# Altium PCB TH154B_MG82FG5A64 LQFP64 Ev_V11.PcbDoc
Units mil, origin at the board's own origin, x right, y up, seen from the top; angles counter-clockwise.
Board outline 2850 x 2110 mil, 2 copper layers (Top Layer, Bottom Layer); 55 components, 79 nets, 354 pads, 133 vias.
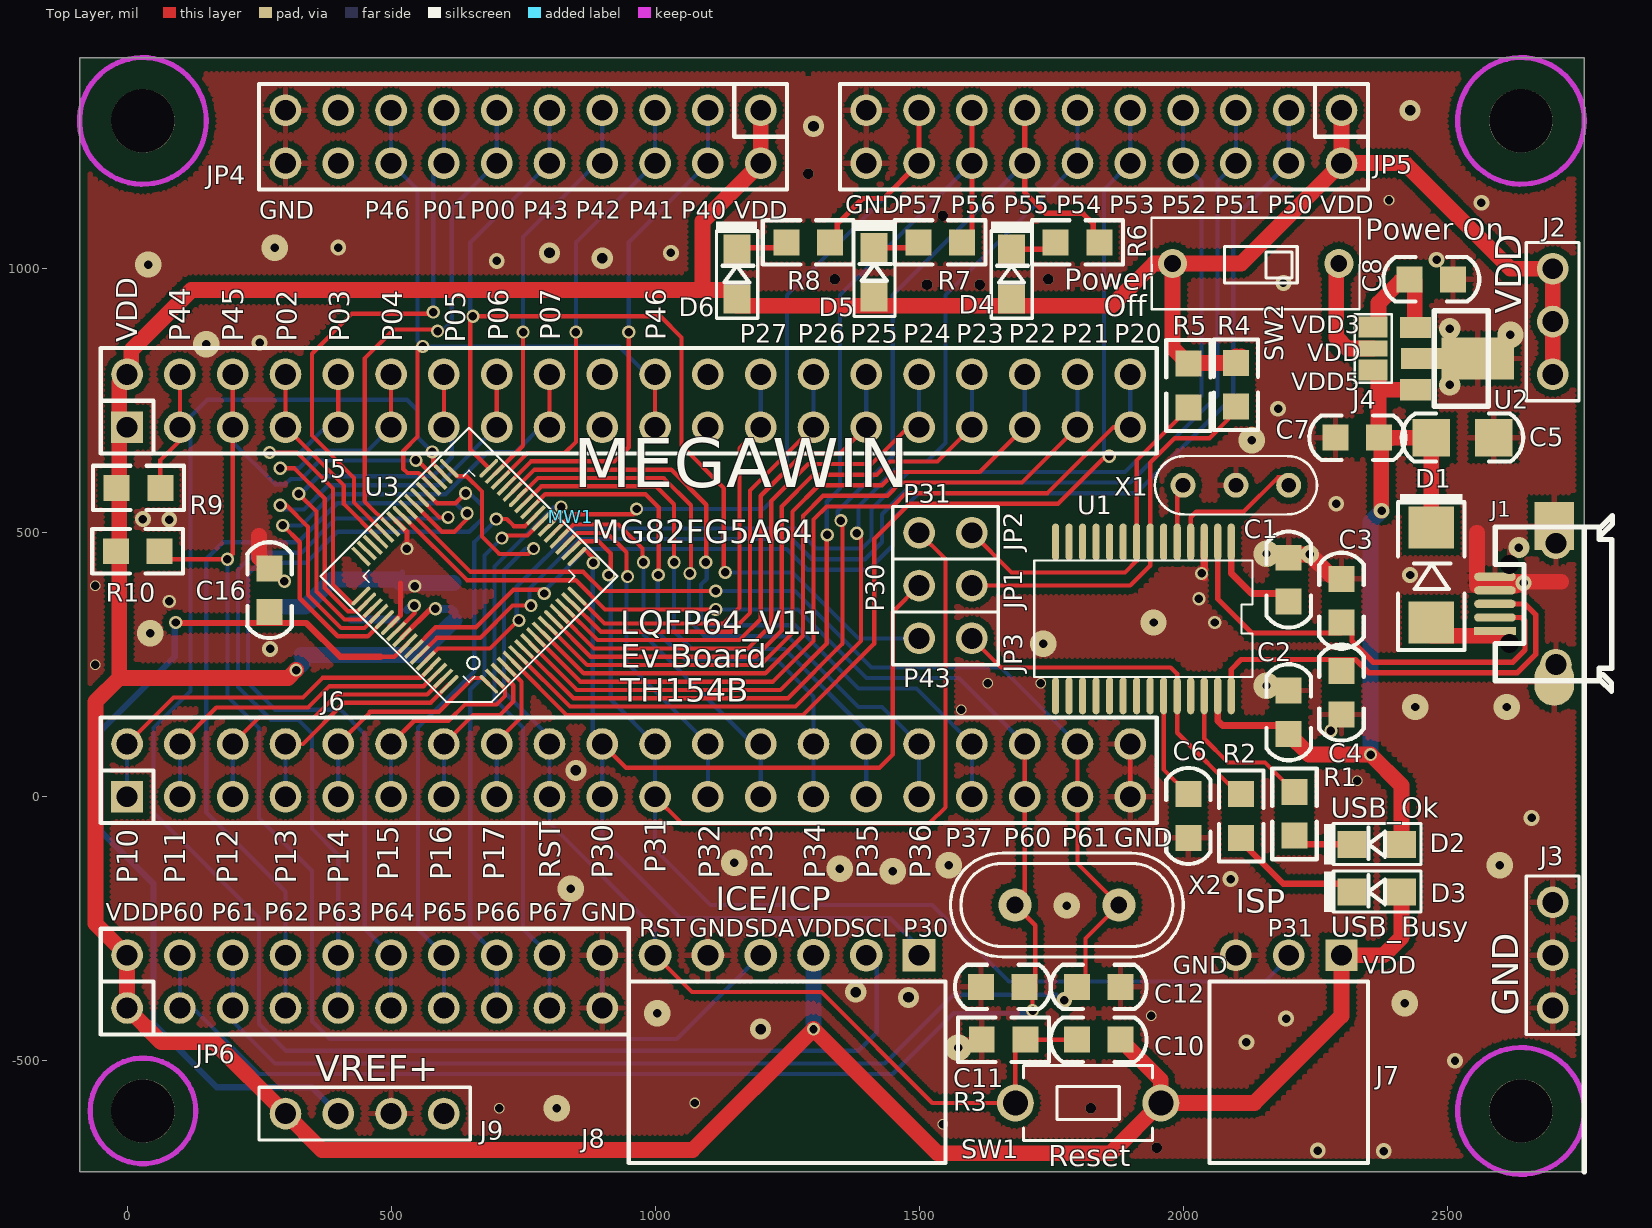
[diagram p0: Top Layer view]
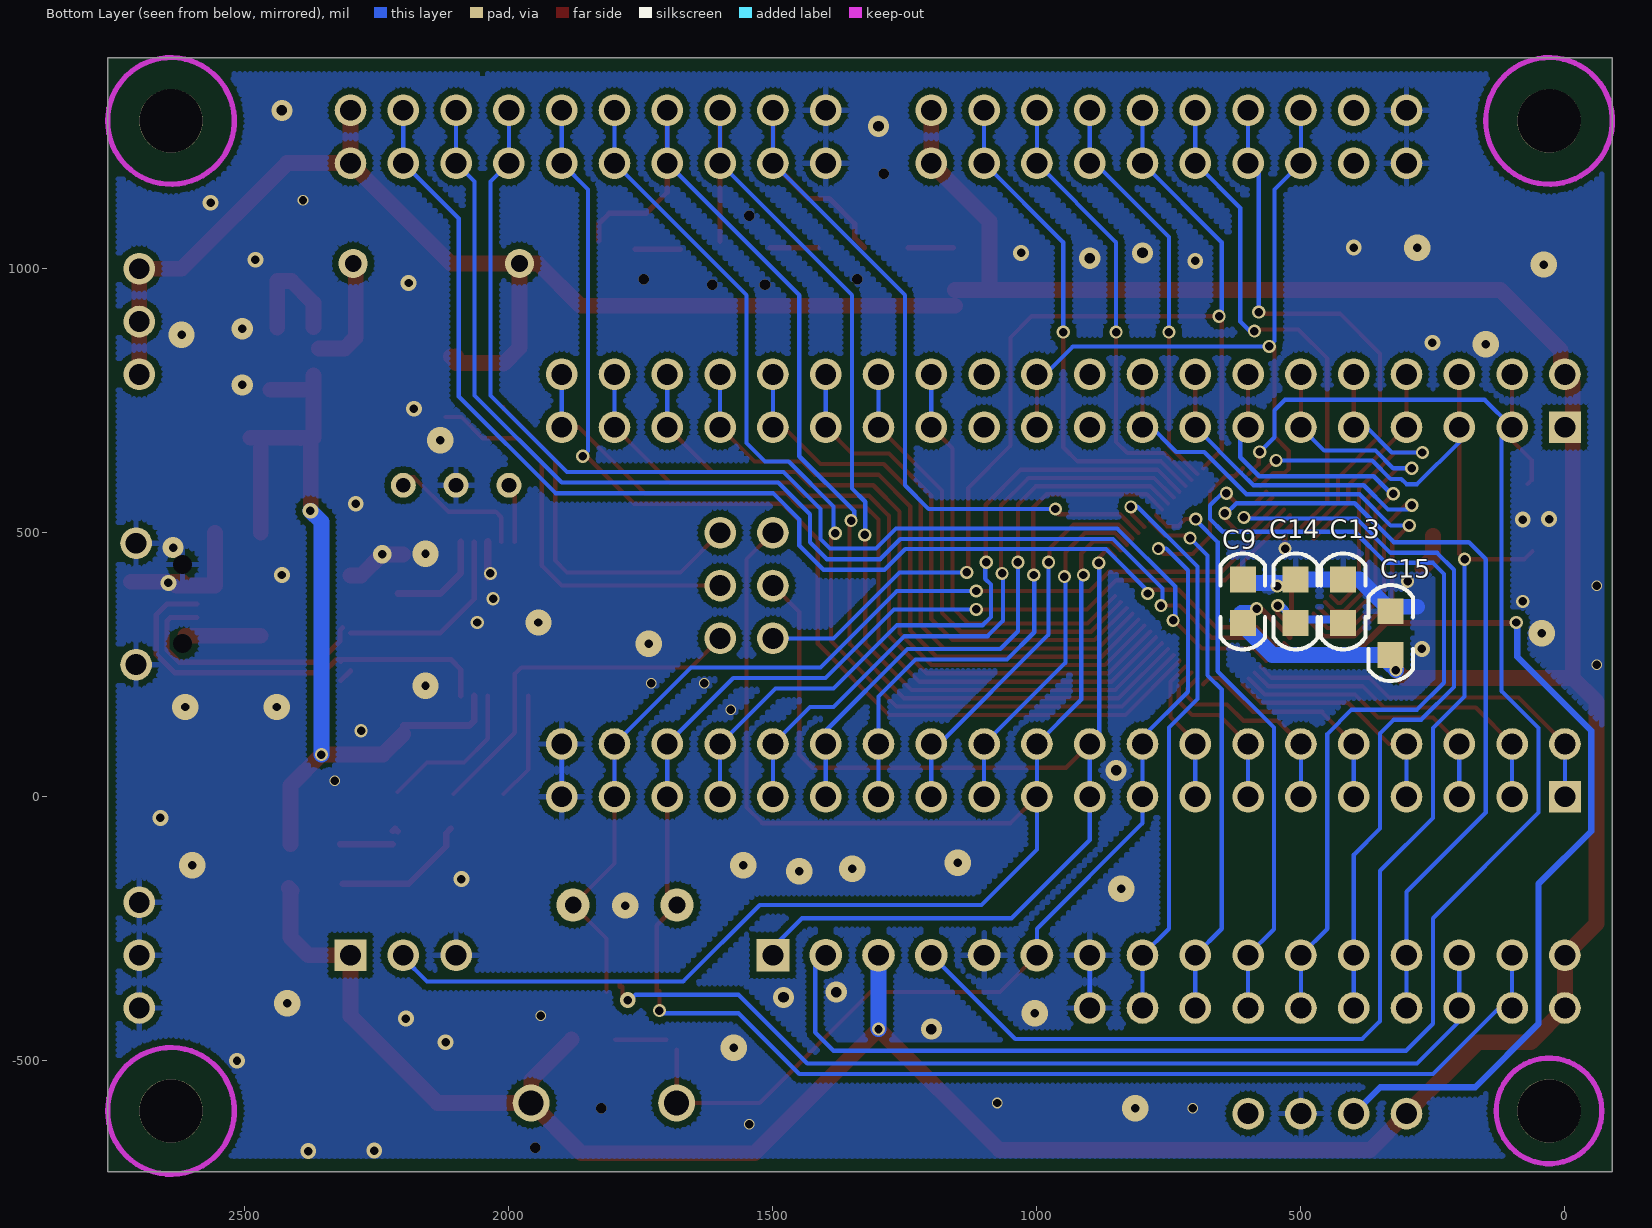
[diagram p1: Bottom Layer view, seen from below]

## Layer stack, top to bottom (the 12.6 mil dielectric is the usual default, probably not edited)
Top Layer: signal copper 1.4
Dielectric: dielectric 12.6, FR-4, Dk 4.8
Bottom Layer: signal copper 1.4

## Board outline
-90,-710 -90,1400 2760,1400 2760,-710

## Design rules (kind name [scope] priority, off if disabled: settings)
Clearance 12 [All] p1 off: gap=12
Clearance 10 [All] p2 off: gap=10
Clearance 6 [All] p3: gap=6
ComponentClearance [All] p1 off: gap=10 collisioncheckmode=3 verticalgap=10 showdistances=FALSE
HoleSize [All] p1: absolutevalues=TRUE maxlimit=500 minlimit=1 maxpercent=80.000 minpercent=20.000
MinimumSolderMaskSliver [All] p1 off: minsoldermaskwidth=10
PolygonConnect VIA [ISVIA] p1: connectstyle=Direct reliefconductorwidth=10 reliefentries=4 polygonreliefangle="90 Angle"
PolygonConnect [All] p2: connectstyle=Relief reliefconductorwidth=10 reliefentries=4 polygonreliefangle="90 Angle"
RoomDefinition "TH154B_MG82FG5A64 LQFP64 Ev_V10" [InComponentClass('TH154B_MG82FG5A64 LQFP64 Ev_V10')] p1: confinementstyle=ConfineIn formatcopy=TRUE lockcomponents=FALSE outline -510,-1145 3015,-1145 3015,1600 -510,1600
RoutingVias [All] p1: holewidth=16 width=25 viastyle="Through Hole" minholewidth=16 minwidth=24 maxholewidth=28 maxwidth=50
SilkToSilkClearance [All] p1 off: silktosilkclearance=10
SilkscreenOverComponentPads [All] p1 off: minsilkscreentomaskgap=10
SolderMaskExpansion [All] p1 off: expansion=4
Width [All] p1: maxlimit=200 minlimit=6 preferedwidth=10
23 further rules are at their usual default settings.

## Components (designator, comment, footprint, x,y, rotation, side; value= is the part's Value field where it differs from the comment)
C1 "4.7uF" 0805C 2200,411.34 r90 top
C2 "0.1uF" 0805C 2200,160 r270 top
C3 "15pF" 0805C 2300,371.34 r90 top
C4 "15pF" 0805C 2300,197.17 r270 top
C5 "4.7uF" 1206C 2529.06,680 r0 top
C6 "0.1uF" 0805C 2010,-36.34 r90 top
C7 "0.1uF" 0805C 2330,680 r180 top
C8 "4.7uF" 0805C 2470,980 r0 top
C9 "0.1uF" 0805C 610,370 r270 bottom
C10 "1u" 0805C 1840,-460 r180 top
C11 "NC" 0805C 1658.66,-360 r180 top
C12 "NC" 0805C 1840,-360 r0 top
C13 "4.7uF" 0805C 420,370 r90 bottom
C14 "0.1uF" 0805C 510,370 r270 bottom
C15 "4.7uF" 0805C 330,310 r90 bottom
C16 "0.1uF" 0805C 270,391.34 r90 top
D1 "1N5817" D5817_SMD_1 2470,420 r270 top
D2 "Yellow" 0805D 2366.92,-90 r180 top
D3 "Red" 0805D 2366.92,-180 r180 top
D4 "Green" 0805D 1675,990 r90 top
D5 "Red" 0805D 1415,993.08 r90 top
D6 "Green" 0805D 1155,990 r90 top
J1 "Micro USB母座" JACK_USB_SMD290X220P065 2590.71,365.28 r180 top
J2 "*" PS3P254 2700,800 r90 top
J3 "*" PS3P254 2700,-200 r270 top
J4 "*" JUMP3_SMD 2360,849 r90 top
J5 "*" PS20X2P254 0,700 r0 top
J6 "*" PS20X2P254 0,0 r0 top
J7 "*" PS3P254f_90 2300,-300 r180 top
J8 "*" PS6P254F_90 1500,-300 r180 top locked
J9 "CON4" PS4P254 300,-600 r0 top
JP1 "JUMPER2" PS2P254 1500,400 r0 top
JP2 "JUMPER2" PS2P254 1500,500 r0 top
JP3 "JUMPER2" PS2P254 1500,300 r0 top
JP4 "*" PS10X2P254 1200,1300 r180 top
JP5 "*" PS10X2P254 2300,1300 r180 top
JP6 "*" PS10X2P254 0,-400 r0 top
MW1 "MW-A4" MEGAWIN_T 840,530 r0 top
R1 "1K" 0805R 2211,-32.34 r270 top
R2 "1K" 0805R 2110,-36.34 r270 top
R3 "47K" 0805R 1660,-460 r0 top
R4 "4.7K" 0805R 2100,780.34 r270 top
R5 "4.7K" 0805R 2010,779 r270 top
R6 "1K" 0805R 1800,1050 r180 top
R7 "1K" 0805R 1540,1050 r180 top
R8 "1K" 0805R 1290,1050 r180 top
R9 "4.7K" 0805R 21.66,585 r180 top
R10 "4.7K" 0805R 20,465 r180 top
SW1 "SW TACT-SPST" SW_T_2P 1820,-580 r180 top
SW2 "-" DIP2_SW 2294.96,1010 r180 top
U1 "MA101_TSSOP28" SSOP28_220P065 1924.84,336.85 r180 top
U2 "AIC1734-33(SOT-89)" SOT89 2440,830 r270 top
U3 "MG82FG5A64" QFP64_7X7P040 647.58,417.62 r135 top (schematic designator U1)
X1 "6MHz" X3P 2200,590 r180 top
X2 "NC" X49U 1780,-205 r180 top

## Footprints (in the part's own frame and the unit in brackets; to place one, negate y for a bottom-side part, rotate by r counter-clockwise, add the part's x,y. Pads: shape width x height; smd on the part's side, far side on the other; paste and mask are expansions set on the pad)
0805C [mm]
  rect 1.25x1.25 smd: 1(-1.05,0) 2(1.05,0)
  silkscreen extent -2.31,-1.07 2.31,1.07
0805D [mm]
  rect 1.4x1.3 smd: 1(-1.192,0) 2(1.192,0)
  silkscreen extent -2.12,-1 2.53,0.98
0805R [mm]
  rect 1.25x1.25 smd: 1(-1.05,0) 2(1.05,0)
  silkscreen extent -2.18,-1.07 2.18,1.07
1206C [mm]
  rect 1.8x1.8 smd: 1(-1.5,0) 2(1.5,0)
  silkscreen extent -2.92,-1.15 2.92,1.16
D5817_SMD_1 [mil]
  rect 80x86.61 smd: 1(90,0) 2(-90,0)
  silkscreen extent -153,-63 142,63
DIP2_SW [mm]
  round 1.4 hole 0.8: 1(0,0) 2(8,0)
  silkscreen extent -1.02,-2.2 9.02,2.2
JACK_USB_SMD290X220P065 [mm]
  rect 1.9x1.8 on Mech2: 0(-2.85,-1.15) 0(-2.85,1.15)
  round 0.8 hole 0.9 unplated: 1(-0.7,1.9) 5(-0.7,-1.9)
  rect 2x0.4 smd: 1(0,1.3)
  oval 2x0.4 smd: 2(0,0.65) 3(0,0) 4(0,-0.65) 5(0,-1.3)
  round 1.524 hole 1: 5(-2.931,2.921) 5(-2.931,-2.921)
  oval 1.9x2.3 smd: 5(-2.85,3.75)
  rect 1.9x2.3 smd: 5(-2.85,-3.75)
  silkscreen extent -5.65,-4.25 -0.01,4.2
JUMP3_SMD [mil]
  rect 40x55 smd: 1(-41,0) 3(41,0)
  rect 30x55 smd: 2(0,0)
  silkscreen extent -65,-35 65,35
MEGAWIN_T [mil]
PS2P254 [mil]
  round 60 hole 39.37: 1(0,0) 2(100,0)
  silkscreen extent -50,-50 150,50
PS3P254 [mil]
  round 60 hole 39.37: 1(0,0) 2(100,0) 3(200,0)
  silkscreen extent -50,-50 250,50
PS3P254f_90 [mil]
  rect 60x60 hole 39.37: 1(0,0)
  round 60 hole 39.37: 2(100,0) 3(200,0)
  silkscreen extent -50,50 250,394
PS4P254 [mil]
  round 60 hole 39.37: 1(0,0) 2(100,0) 3(200,0) 4(300,0)
  silkscreen extent -50,-50 350,50
PS6P254F_90 [mil]
  rect 62x62 hole 39.37: 1(0,0)
  round 62 hole 39.37: 2(100,0) 3(200,0) 4(300,0) 5(400,0) 6(500,0)
  silkscreen extent -50,50 550,394
PS10X2P254 [mil]
  round 60 hole 39.37: 1(0,0) 2(0,100) 3(100,0) 4(100,100) 5(200,0) 6(200,100) 7(300,0) 8(300,100) 9(400,0) 10(400,100) 11(500,0) 12(500,100) 13(600,0) 14(600,100) 15(700,0) 16(700,100) 17(800,0) 18(800,100) 19(900,0) 20(900,100)
  silkscreen extent -50,-50 950,150
PS20X2P254 [mil]
  rect 60x60 hole 39.37: 1(0,0)
  round 60 hole 39.37: 2(0,100) 3(100,0) 4(100,100) 5(200,0) 6(200,100) 7(300,0) 8(300,100) 9(400,0) 10(400,100) 11(500,0) 12(500,100) 13(600,0) 14(600,100) 15(700,0) 16(700,100) 17(800,0) 18(800,100) 19(900,0) 20(900,100) 21(1000,0) 22(1000,100) 23(1100,0) 24(1100,100) 25(1200,0) 26(1200,100) 27(1300,0) 28(1300,100) 29(1400,0) 30(1400,100) 31(1500,0) 32(1500,100) 33(1600,0) 34(1600,100) 35(1700,0) 36(1700,100) 37(1800,0) 38(1800,100) 39(1900,0) 40(1900,100)
  silkscreen extent -50,-50 1950,150
QFP64_7X7P040 [mm]
  oval 1.2x0.19 smd: 1(-4.35,3) 12(-4.35,-1.4) 16(-4.35,-3) 33(4.35,-3) 34(4.35,-2.6) 38(4.35,-1) 41(4.35,0.2)
  rect 1.2x0.19 smd: 2(-4.35,2.6) 3(-4.35,2.2) 4(-4.35,1.8) 5(-4.35,1.4) 6(-4.35,1) 7(-4.35,0.6) 8(-4.35,0.2) 9(-4.35,-0.2) 10(-4.35,-0.6) 11(-4.35,-1) 13(-4.35,-1.8) 14(-4.35,-2.2) 15(-4.35,-2.6) 35(4.35,-2.2) 36(4.35,-1.8) 37(4.35,-1.4) 39(4.35,-0.6) 40(4.35,-0.2) 42(4.35,0.6) 43(4.35,1) 44(4.35,1.4) 45(4.35,1.8) 46(4.35,2.2) 47(4.35,2.6) 48(4.35,3)
  oval 0.19x1.2 smd: 17(-3,-4.35) 27(1,-4.35) 32(3,-4.35) 49(3,4.35) 50(2.6,4.35) 53(1.4,4.35) 54(1,4.35) 64(-3,4.35)
  rect 0.19x1.2 smd: 18(-2.6,-4.35) 19(-2.2,-4.35) 20(-1.8,-4.35) 21(-1.4,-4.35) 22(-1,-4.35) 23(-0.6,-4.35) 24(-0.2,-4.35) 25(0.2,-4.35) 26(0.6,-4.35) 28(1.4,-4.35) 29(1.8,-4.35) 30(2.2,-4.35) 31(2.6,-4.35) 51(2.2,4.35) 52(1.8,4.35) 55(0.6,4.35) 56(0.2,4.35) 57(-0.2,4.35) 58(-0.6,4.35) 59(-1,4.35) 60(-1.4,4.35) 61(-1.8,4.35) 62(-2.2,4.35) 63(-2.6,4.35)
  silkscreen extent -5.05,-5.05 5.05,5.05
SOT89 [mm]
  rect 1.016x1.5 smd: 1(-1.5,0) 3(1.5,0)
  rect 2x3.5 smd: 2(0,3)
  rect 1.016x2.6 smd: 2(0,0.6)
  silkscreen extent -2.3,0.9 2.3,3.5
SSOP28_220P065 [mil]
  oval 13.5x70 smd: 1(-166.34,-145.67) 2(-140.75,-145.67) 3(-115.16,-145.67) 4(-89.57,-145.67) 5(-63.98,-145.67) 6(-38.39,-145.67) 7(-12.79,-145.67) 8(12.8,-145.67) 9(38.39,-145.67) 10(63.98,-145.67) 11(89.57,-145.67) 12(115.16,-145.67) 13(140.75,-145.67) 14(166.34,-145.67) 15(166.34,145.67) 16(140.75,145.67) 17(115.16,145.67) 18(89.57,145.67) 19(63.98,145.67) 20(38.39,145.67) 21(12.8,145.67) 22(-12.79,145.67) 23(-38.39,145.67) 24(-63.98,145.67) 25(-89.57,145.67) 26(-115.16,145.67) 27(-140.75,145.67) 28(-166.34,145.67)
  silkscreen extent -207,-110 207,110
SW_T_2P [mil]
  round 70 hole 47.24: 1(-137.79,0) 2(137.79,0)
  silkscreen extent -122,-71 122,71
X3P [mm]
  round 1.2 hole 0.711: 1(0,0) 2(5.08,0) 3(2.54,0)
  silkscreen extent -1.36,-1.4 6.44,1.4
X49U [mm]
  round 1.6 hole 0.8: 1(-2.5,0) 2(2.5,0)
  silkscreen extent -5.6,-2.5 5.6,2.5

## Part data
C1 C5 C8 C13 C15: library part CAP
C2 C3 C4 C6 C7 C9 C14 C16: library part "CAP NP"
C10: library part C
C11 C12: library part "C NP"
D1: library part DIODE_ZD, "Schottky Diode"
D2 D3 D4 D5 D6: library part LED
J1: library part CON5, "Connector"
J2 J3 J4 J7: library part CON3
J5 J6: library part CON40A
J8: library part CON6
JP4 JP5 JP6: library part CON10X2
R1 R2 R4 R5 R6 R7 R8: library part R_Dup1
R3 R9 R10: library part R
SW2: library part SW-2
U2: library part AIC1734-33(SOT-89)_0
U3: library part MG82FG5A64_LQFP64
X1: library part CRYSTAL_RC
X2: library part CRYSTAL

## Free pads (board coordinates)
  round 120 hole 120 unplated: 0(30,-595) 0(30,1280) 0(2640,-595) 0(2640,1280)

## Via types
v1: diameter 25, hole 16, Top Layer to Bottom Layer, tented both sides, 56 vias
v2: diameter 30, hole 16, Top Layer to Bottom Layer, tented both sides, 23 vias
v3: diameter 50, hole 16, Top Layer to Bottom Layer, tented both sides, 23 vias
v4: diameter 20, hole 16, Top Layer to Bottom Layer, tented both sides, 11 vias
v5: diameter 20, hole 20, Top Layer to Bottom Layer, tented both sides, 8 vias
v6: diameter 40, hole 20, Top Layer to Bottom Layer, tented both sides, 8 vias
v7: diameter 40, hole 16, Top Layer to Bottom Layer, tented both sides, 3 vias
v8: diameter 35, hole 16, Top Layer to Bottom Layer, tented both sides, 1 vias

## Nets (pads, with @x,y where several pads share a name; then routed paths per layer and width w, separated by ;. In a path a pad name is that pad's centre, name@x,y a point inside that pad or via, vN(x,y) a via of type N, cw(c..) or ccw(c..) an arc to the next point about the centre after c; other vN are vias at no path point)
D+: C4.1 J1.3 U1.28 | length 850.7
  Top Layer w10: U1.28 2091.18,241.18 2110,260 2300,260 C4.1@2315,260 ; C4.1 C4.1@2318.51,220 ; C4.1@2318.24,256.76 C4.1@2315,260 ; J1.3 2647.64,365.28 2667.71,345.2 2667.71,269.55 2633.16,235 2351.72,235 2326.72,260 C4.1@2315,260
D-: C3.1 J1.2 U1.2 | length 865
  Top Layer w10: U1.2 2065.59,374.41 2130,310 C3.1@2300,310 ; C3.1@2315,320 2320,315 2320,295 2360,255 2624.87,255 2647.71,277.84 2647.71,333.12 2641.14,339.69 J1.2
GND_POWER: C1.2 C2.1 C3.2 C4.2 C5.2 C6.1 C7.2 C8.2 C9.1 C11.2 C12.2 C13.2 C14.1 C15.2 C16.2 J1.4 J1.5 J3.1 J3.2 J3.3 J6.39 J6.40 J7.3 J8.5 J9.3 JP4.19 JP4.20 JP5.19 JP5.20 JP6.19 JP6.20 R3.1 U1.3 U2.2 U3.42 U3.54 X1.3 | length 1339.3
  Top Layer w8: J6.39 J6.40
  Top Layer w10: U3.54 518,343.71 518,405.01 ; U3.42 530,501.79 v1@530,472.01
  Top Layer w15: v1@2040,416 2040,423 U1.3
  Top Layer w30: 250,494 250,452.68 C16.2 ; C1.2@2200,459 v8(2240,459) 2280,419 C3.2@2300,419 ; 2556.57,400.32 2590.71,400.32 2630,400.32 ; 2556.57,402.91 2556.57,416.46 2556.57,500 ; 2619.25,407.32 2645,407.32 2716.34,407.32
  Bottom Layer w8: JP6.19 JP6.20 ; J6.39 J6.40
  Bottom Layer w10: C14.1@521,405.01 521,411.34 C14.1@521,425.68
  Bottom Layer w30: 280,360 330,360 337.32,360 388.66,411.34 C13.2 C14.1 ; C14.1@518,405.01 521,405.01 545,405.01 610,405.01 C9.1@618,405.01
  other v1: 2280,125 2060,330 80,370 2030,375 545,399 298,408 2035,423 530,470
  other v2: 2380,-671 2255,-670 2515,-500 2120,-465 2195,-420 2090,-156 2660,-40 271,280 2645,405 2430,420 80,525 30,526 2290,555 2180,735 251,860 2190,972.99 700,1015 2480,1017 1030,1030 400,1040 2565,1125
  other v3: 814,-590 1574,-475 1004,-410 2420,-391 1780,-206 840,-174 1450,-141 1350,-136 1556,-130 2600,-130 1150,-125 2440,170 2612.91,170 2158,210 1735,290 44,310 1944,330 2158,460 2130,675 150,857 2620,875 40,1008 280,1040
  other v4: 1545,-620 705,-590 1075,-580 1940,-415 2330,30 1580,165 1630,215 1730,215 -60,250 -60,400 2390,1130
  other v5: 1950,-665 1825,-590 1515,970 1615,970 1340,980 1745,980 1545,1100 1290,1180
  other v6: 1200,-440 1480,-380 1380,-370 850,50 900,1020 800,1030 1300,1270 2430,1300
  other v7: 2636,472 2505,780 2505,886.37
MA101_RX: JP2.2 R5.2 U1.8 | length 683.4
  Top Layer w8: JP2.2 1675,425 1890,425 1912.05,447.05 U1.8 1912.05,637.05 2010,735 R5.2
MA101_TX: JP1.2 R4.2 U1.7 | length 766.4
  Top Layer w8: JP1.2 1900,400 1937.64,437.64 U1.7 1937.64,632.64 1984,679 2050,679 2090,719 2100,719 R4.2@2120,719
NetC1_1: C1.1 U1.1 | length 193.6
  Top Layer w13: U1.1 2091.18,423.82 2130,385 2200,385 C1.1@2210,385
NetC6_2: C6.2 U1.23 | length 205.6
  Top Layer w8: U1.23 1963.23,51.77 C6.2
NetC13_1: C13.1 C14.2 U3.55 | length 176.7
  Top Layer w8: U3.55 545,348.44 v1@545,362
  Bottom Layer w8: C14.2@510,335.5 C14.2@513.67,335.5 ; C14.2@530,352 530,354.01 ; v1@541.49,365.51 v1@545.99,370.01
  Bottom Layer w15: C13.1@425,335.5 C14.2@510,335.5 ; 530,354.01 540.99,365.01 v1@541.49,365.51
  other v1: 544,362
NetD1_1: D1.1 J1.1 | length 142.9
  Top Layer w30: D1.1@2470,305 2590.71,305 J1.1@2612.91,305
NetD2_2: D2.2 R1.2 | length 107.2
  Top Layer w12: R1.2@2210.6,-65 R1.2@2211,-65 ; R1.2@2215,-60 R1.2@2219.84,-64.84 ; R1.2@2220,-90 D2.2
NetD3_2: D3.2 R2.2 | length 263.1
  Top Layer w12: R2.2@2110,-60 2118.84,-68.84 2118.84,-77.68 2118.84,-93.84 2190,-165 D3.2@2315,-165
NetD4_2: D4.2 R6.2 | length 85.6
  Top Layer w10: D4.2 1758.66,1036.92 R6.2@1760.58,1036.92
NetD5_2: D5.2 R7.2 | length 90
  Top Layer w10: D5.2 1498.66,1040 R7.2@1505,1040
NetD6_2: D6.2 R8.2 | length 85.6
  Top Layer w10: D6.2@1158.08,1040 R8.2@1243.66,1040
NetJ4_2: J4.2 SW2.1 | length 217.8
  Top Layer w30: SW2.1@2300,1004.96 2290,994.96 2290,870 2311,849 J4.2
NetU1_4: U1.4 X1.1 | length 263.8
  Top Layer w8: U1.4 2014.41,529.41 2025,540 2115,540 2180,605 X1.1@2200,605
NetU1_5: U1.5 X1.2 | length 127.1
  Top Layer w8: U1.5 1988.82,590 1988.82,593.82 1992.5,597.5 X1.2@2000,605
P00: JP4.11 JP4.12 U3.43 | length 969.7
  Top Layer w8: U3.43 450,559.52 450,830 505,885 v1@585,885
  Bottom Layer w8: v1@585,882 v1(588,882) 597,882 615,900 615,1115 JP4.12 JP4.11
P01: JP4.13 JP4.14 U3.44 | length 1051
  Top Layer w8: U3.44 430,557.25 430,604 350,684 350,839 426,915 v1@580,915
  Bottom Layer w8: v1@580,915 v1(580,918) 580,1180 JP4.14 JP4.13
P02: J5.7 J5.8 U3.45 | length 404.5
  Top Layer w8: J5.8 J5.7 410.49,589.51 410.49,554.49 U3.45
  Bottom Layer w8: J5.7@280,700 J5.7
P03: J5.9 J5.10 U3.49 | length 652.9
  Top Layer w8: v1(270,652.01) 321.99,652.01 390,584 390,402 425.01,366.99 429.93,366.99 U3.49 ; J5.9 J5.10
  Bottom Layer w8: v1(270,652.01) 328.01,652.01 376,700 J5.9
P04: J5.11 J5.12 U3.50 | length 705
  Top Layer w8: v1@300,622.01 316.99,622.01 374.25,564.75 374.25,395.48 418.48,351.24 436.45,351.24 U3.50 ; J5.11 J5.12
  Bottom Layer w8: v1@300,622.01 325.01,622.01 359.01,656.01 456.01,656.01 J5.11
  other v1: 290,622.01
P05: J5.13 J5.14 U3.51 | length 818.8
  Top Layer w8: v1(325,574) 358.5,540.5 358.5,388.95 411.96,335.5 442.97,335.5 U3.51 ; J5.13 J5.14
  Bottom Layer w8: v1(325,574) 329,574 362.01,607.01 579,607.01 615,643.01 615,685 J5.13
P06: J5.15 J5.16 U3.52 | length 959.2
  Top Layer w8: v1(290,552.01) 301.99,552.01 342.76,511.24 342.76,382.43 405.44,319.75 449.5,319.75 U3.52 ; J5.15 J5.16
  Bottom Layer w8: v1(290,552.01) 298.01,544 335,544 381.01,590.01 590.01,590.01 612.55,612.55 ; 604,604 612.55,612.55 ; J5.15 612.55,612.55
P07: J5.17 J5.18 U3.53 | length 1026.8
  Top Layer w8: v1(295,514) 327.01,481.99 327.01,375.91 398.92,304 456.02,304 U3.53 ; J5.17@800,717.01 J5.18
  Bottom Layer w8: v1(295,514) 330,514 389.01,573.01 603,573.01 683.11,653.12 736.11,653.12 791.49,708.51 J5.17@800,717.01
P10: J6.1 J6.2 U3.61 | length 737.2
  Top Layer w8: J6.2 88.01,188.01 333,188.01 370.23,225.24 555.43,225.24 U3.61
  Bottom Layer w8: J6.1 J6.2
P11: J6.3 J6.4 U3.62 | length 643.8
  Top Layer w8: J6.4 169.01,169.01 343,169.01 383.48,209.5 561.95,209.5 U3.62
  Bottom Layer w8: J6.3 J6.4
P12: J6.5 J6.6 U3.63 | length 550.3
  Top Layer w8: J6.6 250,150 353.99,150 397.74,193.75 568.48,193.75 U3.63
  Bottom Layer w8: J6.5 J6.6
P13: J6.7 J6.8 U3.64 | length 534.5
  Top Layer w8: J6.8@327.73,100 J6.8 332.99,100 410.99,178 535,178 ; 485,178 535,178 ; U3.64 575,178 535,178
  Bottom Layer w8: J6.7 J6.8
P14: J6.9 J6.10 U3.1 | length 441.4
  Top Layer w8: J6.10 459.75,159.75 ; 459.75,161 591,161 655,225 673.16,225 U3.1
  Bottom Layer w8: J6.9 J6.10
P15: J6.11 J6.12 U3.2 | length 423.1
  Top Layer w8: J6.12@520,120 J6.12 544,144 609,144 640,175 700,175 715.75,190.75 715.75,204.69 U3.2
  Bottom Layer w8: J6.11 J6.12
P16: J6.13 J6.14 U3.3 | length 329.9
  Top Layer w8: J6.14@599.71,100 J6.14 655,155 706,155 731.5,180.5 731.5,211.21 U3.3
  Bottom Layer w8: J6.13 J6.14
P17: J6.15 J6.16 U3.4 | length 324.3
  Top Layer w8: J6.16 700,104 747.24,151.24 747.24,217.73 ; U3.4 747.24,217.73 ; 747.24,171.24 747.24,217.73
  Bottom Layer w8: J6.15 J6.16
P20: J5.39 J5.40 U3.9 | length 1595
  Top Layer w8: U3.9 858.33,218.01 1223.01,218.01 1300,295 1300,525 1325,550 1450,550 1475,575 1742.99,575 1867.99,700 J5.39
  Bottom Layer w8: J5.39 J5.40
P21: J5.37 J5.38 U3.10 | length 1473.6
  Top Layer w8: U3.10 864.85,233.76 1208.76,233.76 1280,305 1280,532.01 1317.99,570 1440,570 1465,595 1695,595 J5.37
  Bottom Layer w8: J5.37 J5.38
P22: J5.35 J5.36 U3.11 | length 1355.8
  Top Layer w8: U3.11 871.37,249.5 1199.5,249.5 1260,310 1260,540 1310,590 1430,590 1455,615 1615,615 J5.35
  Bottom Layer w8: J5.35 J5.36
P23: J5.33 J5.34 U3.12 | length 1239.2
  Top Layer w8: U3.12 877.89,265.25 1190.25,265.25 1240,315 1240,550 1300,610 1420,610 1445,635 1535,635 J5.33
  Bottom Layer w8: J5.33 J5.34
P24: J5.31 J5.32 U3.13 | length 1119.6
  Top Layer w8: U3.13 884.42,281 1176,281 1220,325 1220,560 1290,630 1410,630 1480,700 J5.31
  Bottom Layer w8: J5.31 J5.32
P25: J5.29 J5.30 U3.14 | length 1001
  Top Layer w8: U3.14 890.94,296.75 1160,296.75 1200,336.75 1200,570 1280,650 1350,650 J5.29 J5.29@1400,702.01
  Bottom Layer w8: J5.29 J5.30
P26: J5.27 J5.28 U3.15 | length 878.5
  Top Layer w8: U3.15 897.46,312.5 1144.15,312.5 1180,348.35 1180,580 J5.27
  Bottom Layer w8: J5.27 J5.28
P27: J5.25 J5.26 U3.16 | length 800
  Top Layer w8: U3.16 903.99,328.24 1130,328.24 1160,358.24 1160,660 J5.25
  Bottom Layer w8: J5.25 J5.26
P30/RXD: J6.19 J6.20 J8.1 JP1.1 U3.17 | length 2199
  Top Layer w8: U3.17 866,469 882,453 882,443 v1@882,442 ; J6.20 945,55 1425,55 1450,80 1450,350 JP1.1
  Bottom Layer w8: v1@882,442 882,118 J6.20 J6.19 900,-82 1048,-230 1445,-230 J8.1@1507.5,-292.5
  other v1: 883,443
P31/TXD: J6.21 J6.22 J7.2 JP2.1 U3.18 | length 3248.4
  Top Layer w8: U3.18 858.73,484 893,484 916,461 916,424 v1(912,420) ; J6.21 1050,-50 1520,-50 1550,-20 1550,450 JP2.1
  Bottom Layer w8: v1@916,420 916,184 J6.22 ; 920,180 J6.22 ; J7.2@2200,-305 2155,-350 1670,-350 1525,-205 1105,-205 1000,-100 J6.21 J6.22
P32: J6.23 J6.24 U3.19 | length 674.3
  Top Layer w8: U3.19 852.21,499.75 909.25,499.75 946,463 v1@946,417
  Bottom Layer w8: v1@946,424 946,417 946,254 J6.24 J6.23
  other v1: 948,417
P33: J6.25 J6.26 U3.20 | length 739.8
  Top Layer w8: U3.20 845.68,515.5 930.5,515.5 976,470 v1@976,455
  Bottom Layer w8: v1@974,444 976,442 978,440 978,307 1192.5,92.5 1200,85 J6.25
  other v1: 978,444
P34: J6.27 J6.28 U3.25 | length 1042
  Top Layer w8: U3.25 791.83,573 982,573 1007,548 v1@1007,420
  Bottom Layer w8: v1@1005,424 1005,420 1005,311.5 1056.5,260 1230,260 1300,190 J6.28 J6.27
  other v1: 1006,420
P35: J6.29 J6.30 U3.26 | length 1119.2
  Top Layer w8: U3.26 784.56,588 1002,588 1036,554 v1(1036,444)
  Bottom Layer w8: v1(1036,444) 1036,313.51 1069.51,280 1245,280 1400,125 J6.30 J6.29
P36: J6.31 J6.32 U3.27 | length 1215.2
  Top Layer w8: U3.27 778.04,603.75 1016.25,603.75 1068,552 v1@1068,424
  Bottom Layer w8: v1@1064,424 1064,423 1064,333.5 1093.32,304.17 1250.83,304.17 1385,170 1430,170 J6.32 J6.31
  other v1: 1066,423
P37: J6.33 J6.34 U3.28 | length 1344.7
  Top Layer w8: U3.28 771.51,619.5 1030.5,619.5 1097,553 v1@1097,444
  Bottom Layer w8: v1(1096,444) v1@1098,442 ; v1@1098,444 v1@1098,442 ; J6.33 J6.34 1495,205 1385,205 1265,325 1102.5,325 1087,340.5 1087,402 1098,413 v1@1098,442
P40: JP4.3 JP4.4 U3.29 | length 981.6
  Top Layer w8: U3.29 764.99,635.24 820,635.24 ; 839.76,635.24 820,635.24 ; v1(950,880) 950,662.01 923.23,635.24 820,635.24
  Bottom Layer w8: v1(950,880) 950,1050 JP4.4 JP4.3
P41: JP4.5 JP4.6 U3.30 | length 902
  Top Layer w8: U3.30 758.47,650.99 770,650.99 ; 809.5,650.99 770,650.99 ; v1(850,880) 850,672.01 828.98,650.99 770,650.99
  Bottom Layer w8: v1(850,880) 850,1050 JP4.6 JP4.5
P42: JP4.7 JP4.8 U3.31 | length 773.3
  Top Layer w8: U3.31 750,664.8 v1(750,880)
  Bottom Layer w8: v1(750,880) 750,1060 895,1205 900,1210 JP4.7
P43: JP3.1 JP4.9 JP4.10 U3.32 | length 2175.1
  Top Layer w8: 650,865 650,760 ; v1@650,905 v1@650,900 ; U3.32 650,657.4 650,760 ; v1@1130,425 1130,585 1050.03,664.97 1050.03,869.97 1010,910 660,910 657.5,907.5 v1@650,900 ; 650,760 v1@650,900
  Bottom Layer w8: v1@650,910 650,1050 JP4.10 JP4.9 ; v1@1130,425 v1(1133,425) 1260,425 1385,300 JP3.1
  other v1: 655,910
P44: J5.3 J5.4 J8.2 R9.1 U3.34 | length 3536.9
  Top Layer w8: R9.1@70.33,592.33 63,599.66 63,638 100,675 J5.3 J5.4 ; v1@580,647.01 580,629.96 U3.34
  Bottom Layer w8: v1(578,653.01) 550,681.01 550,732.01 530,752.01 152.01,752.01 J5.3 120,680 120,200 50,130 50,-30 250,-230 250,-430 301,-481 1385,-481 1420,-446 1420,-350 ; 1420,-440 1420,-350 ; J8.2@1420,-295 1420,-300 1420,-350
P45: J5.5 J5.6 J8.4 R10.1 U3.35 | length 2891.7
  Top Layer w8: R10.1 76.34,450 130,450 ; 150,450 130,450 ; J5.6 J5.5 200,460 v1(190,450) 130,450 ; v1@555,632.69 U3.35
  Bottom Layer w8: v1(190,450) 190,190 250,130 250,-40 350,-140 350,-425 384,-459 1041,-459 J8.4 ; J5.5 200,672.01 280,592.01 300,592.01 310,602.01 330.01,602.01 365.01,637.01 480,637.01 ; 443,637.01 480,637.01 ; v1(547,637.01) 480,637.01 ; v1@550,634.01 v1@551,635.01
P46: J5.21 J5.22 JP4.15 JP4.16 U3.36 | length 1343.9
  Top Layer w8: v1@550,853 550,682.01 523,655.01 523,621.01 530.87,613.14 552.28,613.14 U3.36 ; J5.21 J5.22
  Bottom Layer w8: JP4.15 JP4.16 550,1150 550,863 v1(560,853) 932,853 985,800 J5.22
P50: JP5.3 JP5.4 U3.58 | length 2405.1
  Top Layer w8: U3.58 584.37,321 661,321 732.01,392.01 782.99,392.01 v1(790,385)
  Bottom Layer w8: v1(790,385) 790,390 869,469 1249.43,469 1288.43,430 1404,430 1450,476 1450,525 1500,575 1912.01,575 2095,757.99 2095,1095 JP5.4 JP5.3
P51: JP5.5 JP5.6 U3.59 | length 2370.2
  Top Layer w8: U3.59 586.64,301 669,301 730,362 v1(765,362)
  Bottom Layer w8: v1(765,362) 767,364 762,369 762,394.26 855.74,488 1258.72,488 1296.72,450 1398,450 1430,482 1430,535 1490,595 1900,595 2065,760 2065,1165 JP5.6 ; JP5.5 JP5.6 ; JP5.6@2110,1190 JP5.6
P52: JP5.7 JP5.8 U3.60 | length 2340.7
  Top Layer w8: U3.60 588.92,281 687,281 741,335 v1@744,338
  Bottom Layer w8: v1@744,338 738,344 738,398 848,508 1267,508 1305,470 1392,470 1410,488 1410,545 1480,615 1890,615 2035,760 2035,1165 JP5.8 JP5.7
  other v1: 742,334
P53: JP5.9 JP5.10 U3.5 | length 2160.3
  Top Layer w8: U3.5 832.25,155 1280,155 1415,290 1415,488 1482,555 1762.99,555 v1@1850,642.01
  Bottom Layer w8: v1(1860,645) 1850,655 1850,1150 JP5.10 JP5.9
P54: JP5.11 JP5.12 U3.6 | length 1939.4
  Top Layer w8: U3.6 838.77,170.75 1265.75,170.75 1390,295 1390,499 1390,500 v1@1386.5,503.5
  Bottom Layer w8: v1@1385,510 1385,550 1470,635 1514.99,635 1550,670.01 1550,950 JP5.12 JP5.11
  other v1: 1382,499
P55: JP5.13 JP5.14 R6.1 U3.7 | length 2210.2
  Top Layer w8: U3.7 845.3,186.5 1251.5,186.5 1355,290 1355,523 v1@1355,524 ; JP5.13 JP5.13@1718.66,1281.34
  Top Layer w10: JP5.13 JP5.14 1700,1145 1740,1105 1810,1105 1830,1085 R6.1@1830,1053.26
  Bottom Layer w8: v1@1346,523 1346,541 1450,645 1450,950 JP5.14 JP5.13
  other v1: 1352,523
P56: JP5.15 JP5.16 R7.1 U3.8 | length 2019.2
  Top Layer w8: U3.8 851.82,202.24 1237.24,202.24 1325,290 v1@1325,490
  Top Layer w10: R7.1@1600,1052.32 JP5.16 ; JP5.15 JP5.16 ; JP5.16@1613.16,1186.84 JP5.16
  Bottom Layer w8: v1@1325,496 1325,558.73 1350,583.73 1350,950 JP5.16 JP5.15
  other v1: 1326,496
P57: JP5.17 JP5.18 R8.1 U3.21 | length 1647.3
  Top Layer w8: U3.21 842.92,535 959.5,535 965,540.5 v1@965.51,540.5
  Top Layer w10: R8.1@1326.34,1040 1333.84,1047.5 1345,1058.66 1345,1085 1392.99,1132.99 1432.99,1132.99 JP5.18 JP5.17
  Bottom Layer w8: v1(965,545) 1205,545 1250,590 1250,950 JP5.18 JP5.17
P60: C11.1 J6.35 J6.36 JP6.3 JP6.4 U3.41 X2.2 | length 3808.5
  Top Layer w8: U3.41 643.8,410.26 849.74,410.26 905.26,354.74 v1(1115,354.74) ; J6.36 J6.35 1700,-186.58 X2.2 1720,-243.42 1720,-360 C11.1@1720,-370 ; v1@1715,-410 v1(1715,-405) C11.1@1715,-368
  Bottom Layer w8: JP6.4 JP6.3 125,-400 250,-525 1450,-525 1565,-410 v1@1715,-410 ; v1(1115,354.74) 1270.41,354.74 1400.15,225 1575,225 J6.36 J6.35
P61: C12.1 J6.37 J6.38 JP6.5 JP6.6 U3.40 X2.1 | length 3902.4
  Top Layer w8: U3.40 650.32,426.01 863.99,426.01 900.26,389.74 v1(1115,389.74) ; v2@1785,-385 C12.1@1785,-360 ; C12.1@1790,-360 C12.1@1790,-353 ; J6.38 J6.37 1800,-126.58 X2.1 1815,-268.42 1815,-360 C12.1@1815,-370
  Bottom Layer w8: JP6.6 JP6.5 200,-425 280,-505 1435,-505 1565,-375 1760,-375 v2@1772.5,-387.5 ; v1(1115,389.74) 1265.26,389.74 1410,245 1655,245 J6.38 J6.37
  other v2: 1775,-385
P62: JP6.7 JP6.8 U3.39 | length 1635.3
  Top Layer w8: 567.53,531.08 U3.39 596.59,502.01 620.01,502.01 644,526 v1(644,537)
  Bottom Layer w8: JP6.7 JP6.8 300,-180 150,-30 150,450 182,482 324,482 398.01,556.01 622,556.01 v1@642.51,535.51
P63: JP6.9 JP6.10 U3.38 | length 1471.5
  Top Layer w8: U3.38 591.88,529 v1(608,529)
  Bottom Layer w8: JP6.9@400,-425 JP6.9 JP6.10 400,-110 350,-60 350,120 324,146 272.13,146 210,208.13 210,430 242,462 330,462 395.01,527.01 v1@608,527.01
P64: JP6.11 JP6.12 U3.37 | length 1649.6
  Top Layer w8: U3.37 587.14,556.01 622,556.01 v1(641,575.01)
  Bottom Layer w8: JP6.11 JP6.12 450,-250 450,119 404,165 280,165 229,216 229,422.13 249.87,443 339,443 398,502 648,502 672,526 672,551.99 v1@644.99,579
P65: JP6.13 JP6.14 U3.24 | length 1103.3
  Top Layer w8: v1@705,526 719,526 732.46,512.54 753.65,512.54 U3.24
  Bottom Layer w8: JP6.13 JP6.14 551,-251 551,131 657.71,237.71 657.71,482.71 695,520 699,520 705,520 705,526 v1@705,530
  other v1: 699,526
P66: JP6.15 JP6.16 U3.23 | length 1024.2
  Top Layer w8: v1(710,490) 715,495 758.37,495 U3.23
  Bottom Layer w8: JP6.15 JP6.16 650,-250 650,203 677,230 677,457 v1(710,490)
P67: JP6.17 JP6.18 U3.22 | length 1099.1
  Top Layer w8: U3.22 820,534.36 820,549 v1@820,550
  Bottom Layer w8: JP6.17 JP6.18 750,-250 750,131 696,185 696,436 810,550 v1@820,550
  other v1: 822,549
RST: C10.2 J6.17 J6.18 J8.6 R3.2 SW1.2 U3.33 | length 2243
  Top Layer w8: U3.33 625.31,606.92 643.09,606.92 672,578.01 672,493 705,460 ; 750,460 705,460 ; v1(770,470) 760,460 705,460 ; J8.6 1070,-370 1315,-370 1525,-580 SW1.2 R3.2@1682.21,-479.13 ; R3.2 C10.2
  Bottom Layer w8: v1(770,470) 755,470 714,429 714,199 800,113 J6.18 J6.17 800,-50 1000,-250 J8.6
USB_BUSY: JP3.2 R2.1 U1.24 | length 692.6
  Top Layer w8: JP3.2 1655,245 1976.61,245 1988.82,232.8 U1.24 1988.82,121.18 R2.1@2105,5
USB_OK: R1.1 U1.26 | length 294
  Top Layer w8: U1.26 2040,110 2085,65 2155,65 R1.1
VDD: C9.2 C10.1 C15.1 D3.1 D4.1 D5.1 D6.1 J2.1 J2.2 J2.3 J5.1 J5.2 J7.1 J8.3 J9.1 JP4.1 JP4.2 JP5.1 JP5.2 JP6.1 JP6.2 R4.1 R5.1 R9.2 R10.2 SW1.1 SW2.2 U3.56 | length 9370.2
  Top Layer w10: U3.56 v1@578.42,359.58
  Top Layer w30: -14.91,225.09 -14.91,465 -14.91,585 -14.91,700 -14.91,785.09 J5.2 ; J5.2@7.84,804.59 7.84,845.58 122.26,960 1090,960 ; v1(320,240) 305,225 -15,225 -60,180 -60,-240 JP6.2 JP6.1 65,-465 165,-465 J9.1 369,-669 1071,-669 v1(1300,-440) 1535,-675 1862.79,-675 SW1.1 ; D6.1@1155,930 1415,930 1675,930 1865,930 1945,1010 SW2.2 ; D6.1@1155,960 1090,960 ; JP4.1 JP4.2 1090,1090 1090,960 ; C10.1 1957.79,-536.46 SW1.1 ; R5.1 1980,850.34 SW2.2 ; R5.1@2011.34,821.68 R4.1 R4.1@2100,829 ; R4.1@2100,833.95 R4.1@2100,829 ; R4.1@2110,834.05 2104.95,829 R4.1@2100,829 ; J7.1@2300,-290 J7.1 ; JP5.1 JP5.2 ; D3.1@2411.92,-178.08 D3.1@2416.92,-173.08 ; D3.1 2413.84,-266.16 2380,-300 J7.1 ; J2.1 J2.2 J2.3 2620,1000 2420,1200 JP5.2 ; SW1.1 2135,-580 2300,-415 J7.1 ; SW2.2 2110,1010 JP5.2
  Bottom Layer w15: v1(584,356) 610,356 614.67,356 C9.2@620,350.67
  Bottom Layer w30: v1(320,240) C15.1@332.5,252.5 ; C15.1 554.31,268.66 612.15,326.51 C9.2@620,334.36 ; v1(1300,-440) J8.3
VDD3: C8.1 J4.3 U2.1 | length 218.7
  Top Layer w30: J4.3@2370,890 2370,935 2411.77,976.77 2428.66,976.77 2438.66,976.77 U2.1@2438.66,889.06
VDD5: C2.2 C5.1 C7.1 D1.2 D2.1 J4.1 U1.27 U2.3 | length 1706
  Top Layer w13: U1.27 2065.59,144.41 2075,135 2150,135 ; 2085,135 2150,135 ; C2.2@2200,135 2150,135
  Top Layer w30: C2.2 2238.66,80 v1(2355,80) 2413.84,21.16 D2.1 ; J4.1@2370,798 2370,770.94 ; v2@2375.38,541.76 C7.1@2375.38,680 ; C7.1@2395,679.06 C7.1@2395,680 ; U2.3@2451.89,770.94 U2.3 2370,770.94 ; D1.2@2470,500 D1.2 C5.1@2470,660.94 ; C5.1@2490,680 C5.1 C7.1@2395,680 ; 2370,770.94 2370,680 C7.1 C7.1@2375.38,680 ; C7.1@2375.38,680 C7.1@2395,680
  Bottom Layer w30: v1(2355,80) 2355,520.73 v2(2376.04,541.76)
VREF+: C16.1 J9.2 U3.57 | length 1832.5
  Top Layer w8: 403.66,265 506.1,265 U3.57
  Top Layer w12: v1@92,329 270,329 339.66,329 403.66,265 480,265
  Bottom Layer w12: v1@90,329 90,265 -50,125 -50,-65 50,-165 50,-430 170,-550 350,-550 J9.2
  other v1: 92,330
pads on no net: J1.0 J5.19 J5.20 J5.23 J5.24 J9.4 JP4.17 JP4.18 U1.6 U1.9 U1.10 U1.11 U1.12 U1.13 U1.14 U1.15 U1.16 U1.17 U1.18 U1.19 U1.20 U1.21 U1.22 U1.25 U3.46 U3.47 U3.48

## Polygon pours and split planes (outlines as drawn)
GND_POWER on Bottom Layer "Bottom Layer-No Net" (hatched 90Degree grid 10 track 10, remove dead copper, pour order 1001): -70,-681 2740,-681 2740,1370 -70,1370
GND_POWER on Top Layer "Bottom Layer-No Net" (hatched 90Degree grid 10 track 10, remove dead copper, pour order 1001): -70,-681 2740,-681 2740,1370 -70,1370

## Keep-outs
Keep-Out Layer:
  circle w10: c2640,1280 r120
  circle w10: c30,-595 r100
  circle w10: c30,1280 r120
  circle w10: c2640,-595 r120

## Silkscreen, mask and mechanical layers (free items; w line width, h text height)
Top Overlay:
  lines w10: 2760,-710 2760,352.99
  text "GND" at 1360,1105 h33
  text "P57" at 1460,1105 h33
  text "P56" at 1560,1105 h33
  text "P55" at 1660,1105 h33
  text "P54" at 1760,1105 h33
  text "P53" at 1860,1105 h33
  text "P52" at 1960,1105 h33
  text "P51" at 2060,1105 h33
  text "P50" at 2160,1105 h33
  text "VDD" at 2260,1105 h33
  text "GND" at 250,1095 h33
  text "P46" at 450,1095 h33
  text "P01" at 560,1095 h33
  text "P00" at 650,1095 h33
  text "P43" at 750,1095 h33
  text "P42" at 850,1095 h33
  text "P41" at 950,1095 h33
  text "P40" at 1050,1095 h33
  text "VDD" at 1150,1095 h33
  text "Power On" at 2345,1055 h40
  text "Power" at 1775,960 h40
  text "VDD" at 2640,915 h50 r90
  text "Off" at 1850,910 h40
  text "VDD3" at 2205,878 h33
  text "P07" at 820,865 h38 r90
  text "P46" at 1020,865 h38 r90
  text "P06" at 722,864 h38 r90
  text "P44" at 120,862 h40 r90
  text "P45" at 220,862 h40 r90
  text "P02" at 321,862 h38 r90
  text "P03" at 421,862 h38 r90
  text "P04" at 521,862 h38 r90
  text "VDD" at 19,861 h40 r90
  text "P05" at 640,860 h38 r90
  text "P27" at 1160,860 h35
  text "P26" at 1270,860 h35
  text "P25" at 1370,860 h35
  text "P24" at 1470,860 h35
  text "P23" at 1570,860 h35
  text "P22" at 1670,860 h35
  text "P21" at 1770,860 h35
  text "P20" at 1870,860 h35
  text "VDD" at 2235,825 h33
  text "VDD5" at 2205,770 h33
  text "P31" at 1470,557 h35
  text "MG82FG5A64" at 880,480 h45
  text "P30" at 1433.66,350 h35 r90
  text "LQFP64_V11" at 934,307.44 h45
  text "Ev Board" at 934,244.45 h45
  text "P43" at 1470,207 h35
  text "TH154B" at 934,179.76 h45
  text "USB_Ok" at 2280,-40 h38
  text "P37" at 1550,-95 h35
  text "P60" at 1660,-95 h35
  text "P61" at 1770,-95 h35.43
  text "GND" at 1870,-95 h35.43
  text "P31" at 1020,-145 h40 r90
  text "RST" at 820,-155 h40 r90
  text "P30" at 920,-155 h40 r90
  text "P32" at 1122,-155 h40 r90
  text "P33" at 1222,-155 h40 r90
  text "P34" at 1322,-155 h40 r90
  text "P35" at 1422,-155 h40 r90
  text "P36" at 1522,-155 h40 r90
  text "P15" at 513.95,-158.05 h40 r90
  text "P16" at 613.95,-158.05 h40 r90
  text "P17" at 713.95,-158.05 h40 r90
  text "P10" at 20,-165 h40 r90
  text "P11" at 110,-165 h40 r90
  text "P12" at 210,-165 h40 r90
  text "P13" at 320,-165 h40 r90
  text "P14" at 420,-165 h40 r90
  text "ICE/ICP" at 1115,-215 h45
  text "ISP" at 2100,-220 h45
  text "VDD" at -40,-235 h33
  text "P60" at 60,-235 h33
  text "P61" at 160,-235 h33
  text "P62" at 260,-235 h33
  text "P63" at 360,-235 h33
  text "P64" at 460,-235 h33
  text "P65" at 560,-235 h33
  text "P66" at 660,-235 h33
  text "P67" at 760,-235 h33
  text "GND" at 860,-235 h33
  text "RST" at 970,-265 h33
  text "GND" at 1065,-265 h33
  text "SDA" at 1170,-265 h33
  text "VDD" at 1270,-265 h33
  text "SCL" at 1370,-265 h33
  text "P30" at 1470,-265 h33
  text "P31" at 2160,-265 h33
  text "USB_Busy" at 2280,-265 h38
  text "GND" at 1980,-335 h33
  text "VDD" at 2340,-335 h33
  text "GND" at 2635,-415 h50 r90
  text "VREF+" at 356,-539 h50
  text "Reset" at 1745,-700 h40
Mechanical 1:
  the board outline again, w13
Mechanical 2:
  circle w10: c2640,1280 r120
  circle w10: c30,-595 r100
  circle w10: c30,1280 r120
  circle w10: c2640,-595 r120

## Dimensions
-90,-710 to 2760,-710 on Top Overlay
-90,1400 to -90,-710 on Top Overlay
